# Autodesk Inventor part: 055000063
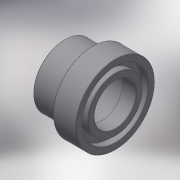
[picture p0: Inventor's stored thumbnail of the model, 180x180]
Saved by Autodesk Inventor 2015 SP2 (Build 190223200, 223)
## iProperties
Created: 2017-10
Part Number: 055000063
Material: Generic
Description: PLASSON FLANGE AD.+O-RING-CE 63
Document SubType Name: Modeling
Designer: KIM
Density: 1 g/cm^3
Appearance: Default
Author: KIM
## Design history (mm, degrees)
derived "055000.ipt"
feature "Solid1::055000.ipt"
tag "TaggingFeature1"
body "Solid1"
other parameters: "d0" = 46, "d1" = 76, "d2" = 63, "d3" = 56.7, "d4" = 14, "d5" = 38, "d8" = 4.2, "d11" = 0.63, "d12" = 4.2, "d15" = 4.995, "d_" = 63, "E_" = 76, "l_" = 38, "B_" = 14, "H_" = 46, "d14" = 16.65
